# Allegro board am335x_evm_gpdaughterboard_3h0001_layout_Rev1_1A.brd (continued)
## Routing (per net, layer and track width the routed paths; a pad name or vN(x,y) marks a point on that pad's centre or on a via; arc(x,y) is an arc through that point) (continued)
NOR_A9: length 31.9
  TOP w0.121: v1(106.08,111.08) 119.41,111.08 120.55,109.93 U4.3 ; v2(105.15,96.97) U3.B6
  LY3 w0.102: v2(105.15,96.97) 105.57,97.4 105.57,98.59 106.8,99.82 106.8,102.53 106.32,103.01
  LY3 w0.121: v1(106.08,111.08) 106.08,103.25 106.32,103.01
NOR_A10: length 29.4
  TOP w0.121: v2(106.14,96.97) U3.A6 ; U4.5 119.75,109.94 119.05,110.63 106.95,110.63 v1(106.59,110.27)
  LY3 w0.102: v2(106.14,96.97) 106.72,97.54 106.72,98.72 107.23,99.22 107.23,102.65 106.87,103.01
  LY3 w0.121: 106.87,103.01 106.59,103.29 v1(106.59,110.27)
NOR_A11: length 27.6
  TOP w0.121: v1(104.05,105.83) 104.39,106.17 117.83,106.17 119.35,107.69 U4.6 ; v2(104.15,96.97) U3.C6
  LY3 w0.102: 104.2,103.01 104.69,102.53 104.69,99.07 103.75,98.13 103.75,97.36 v2(104.15,96.97)
  LY3 w0.121: 104.2,103.01 104.05,103.16 v1(104.05,105.83)
NOR_A12: length 16.2
  TOP w0.121: v2(103.15,96.97) U3.D6 ; v1(115.58,97.75) 115.68,97.65 115.91,97.65 116.36,97.2 116.37,97.2 116.55,97.02 U2.13
  LY6 w0.102: v2(103.15,96.97) 103.56,96.56 107.23,96.56 107.5,96.28
  LY6 w0.121: v1(115.58,97.75) 115.55,97.71 115.19,97.71 113.76,96.28 107.5,96.28
NOR_A13: length 14.4
  TOP w0.121: v2(105.15,95.97) U3.B7 ; U2.14 116.15,95.21 116.33,95.03 116.36,95.03 v1(116.55,94.83)
  LY6 w0.102: 107.7,95.54 105.61,95.54 105.53,95.62 105.5,95.62 v2(105.15,95.97)
  LY6 w0.121: v1(116.55,94.83) 115.46,95.92 108.08,95.92 107.7,95.54
NOR_A14: length 13.8
  TOP w0.102: v2(106.14,95.97) 106.19,95.92 107.5,95.92
  TOP w0.121: U2.16 115.35,97.3 115.01,97.64 115.01,98.81 114.75,99.07 111.01,99.07 107.86,95.92 107.5,95.92 ; v2(106.14,95.97) U3.A7
NOR_A15: length 14.1
  TOP w0.121: U2.17 v1(114.95,94.8) ; v2(104.15,95.97) U3.C7
  LY6 w0.102: 107.5,94.35 104.99,94.35 104.3,95.03 104.3,95.81 v2(104.15,95.97)
  LY6 w0.121: v1(114.95,94.8) 114.5,94.35 107.5,94.35
NOR_A16: length 17.7
  TOP w0.102: 107.5,94.29 107.48,94.27 102.78,94.27 102.24,94.81 102.24,96.06 U3.D7
  TOP w0.121: 107.5,94.29 111.6,98.4 113.77,98.4 114.11,98.06 114.11,97.52 114.15,97.48 U2.19
NOR_A17: length 19.5
  TOP w0.121: v1(100.82,92.98) 101.74,93.89 113.32,93.89 113.75,94.32 U2.20 ; v2(101.15,95.97) U3.E7
  LY3 w0.102: 100.34,94.21 100.34,94.88 101.15,95.68 v2(101.15,95.97)
  LY3 w0.121: 100.34,94.21 100.34,93.46 v1(100.82,92.98)
NOR_A18: length 12.6
  TOP w0.121: v1(113.58,97.7) 112.95,97.08 U2.22 ; v2(105.15,100.97) U3.B3
  LY6 w0.102: 107.5,98.86 107.26,98.86 v2(105.15,100.97)
  LY6 w0.121: 107.5,98.86 112.92,98.86 113.58,98.21 v1(113.58,97.7)
NOR_A19: length 12.2
  TOP w0.121: v2(104.15,99.97) U3.C4 ; U2.23 112.55,97.19 112.59,97.24 112.59,97.73 v1(112.81,97.95)
  LY6 w0.102: v2(104.15,99.97) 104.69,99.43 105.75,99.43 107.28,97.89 107.92,97.89
  LY6 w0.121: v1(112.81,97.95) 109.37,97.95 109.31,97.89 107.92,97.89
NOR_A20: length 26.3
  TOP w0.121: U4.8 118.55,107.31 117.85,106.61 v1(108.14,106.61) ; v2(103.15,97.97) U3.D5
  BOTTOM w0.102: 107.5,101.79 107.23,101.51 103.92,101.51 103.55,101.14 103.55,100.76 103.29,100.49 102.91,100.49 102.53,100.11 102.53,98.59 v2(103.15,97.97)
  BOTTOM w0.121: v1(108.14,106.61) 108.14,102.43 107.5,101.79
NOR_A21: length 23.6
  TOP w0.121: U4.9 118.15,107.73 118.19,107.69 118.19,107.31 117.94,107.05 112,107.05 111.98,107.04 111.61,107.04 111.6,107.05 109.17,107.05 v1(108.87,107.35) ; v2(103.15,99.97) U3.D4
  BOTTOM w0.102: v2(103.15,99.97) 103.67,100.49 107.23,100.49 107.5,100.77
  BOTTOM w0.121: v1(108.87,107.35) 108.87,104.68 108.59,104.39 108.59,101.85 107.5,100.77
NOR_A22: length 26.4
  TOP w0.102: 107.5,98.91 104.09,98.91 U3.C5 ; 109.95,99.48 109.39,98.91
  TOP w0.121: U4.11 v1(117.35,110.07) ; v1(115.51,98.64) 115.51,99.12 115.15,99.48 114.85,99.48 114.85,99.48 114.28,99.48 114.28,99.48 109.95,99.48 ; 109.39,98.91 107.5,98.91
  LY3 w0.121: v1(115.51,98.64) 116.19,99.33 116.19,104.63 117.13,105.57 117.13,109.85 v1(117.35,110.07)
NOR_A23: length 23.1
  TOP w0.102: v2(105.15,94.97) 107.5,94.97
  TOP w0.121: v1(116.34,107.5) 116.37,107.53 116.83,107.53 116.95,107.65 U4.12 ; v1(114.57,98.63) 113.94,98.63 113.93,98.64 111.25,98.64 107.58,94.97 107.5,94.97 ; v2(105.15,94.97) U3.B8
  BOTTOM w0.121: v1(116.34,107.5) 115.3,106.46 115.3,100.6 114.57,99.86 v1(114.57,98.63)
NOR_BYTEN: length 4.5
  TOP w0.121: v2(100.15,95.97) U3.F7
  BOTTOM w0.102: v2(100.15,95.97) 100.15,94.82 100.15,94.21
  BOTTOM w0.121: R259.2 100.11,92.37 R14.1 100.15,93.92 100.15,94.21
NOR_CEN: length 129.8
  TOP w0.121: U43.C8 v2(96.34,76.13) ; U2.48 121.9,90.4 v1(121.96,90.33) ; v1(120.43,100.01) 121.35,100.93 U4.48 ; v1(112.15,101.84) U4.25 ; U2.25 v1(111.54,90.4) 101.43,90.4 100.99,89.95 93.76,89.95 93.32,90.4 v1(92.87,90.4) U6.48 ; U6.25 v1(82.21,90.4) ; v2(100.15,101.97) U3.F2
  LY3 w0.121: v1(112.15,101.84) 111.1,100.79 111.1,90.84 v1(111.54,90.4)
  LY6 w0.102: v2(102.15,100.96) 102.15,102.15 ; 102.15,102.15 102.4,102.15 103.26,103.01 ; 102.15,102.15 101.89,102.4 100.75,102.4 100.32,101.97 v2(100.15,101.97)
  LY6 w0.121: v1(79.2,90.4) v1(82.21,90.4) 82.65,90.4 82.71,90.33 92.37,90.33 92.43,90.4 v1(92.87,90.4) ; v1(121.96,90.33) 118.63,90.33 118.57,90.4 v1(111.54,90.4) ; v1(89.11,84.68) 88.5,85.29 84.67,85.29 83.92,84.54 82.92,84.54 82.08,85.38 v1(79.2,85.38) ; 103.26,103.01 103.35,103.09 106.79,103.09 108.01,101.87 108.95,101.87 112.12,101.87 v1(112.15,101.84) 112.15,101.79 113.45,100.49 116.75,100.49 117.23,100.01 v1(120.43,100.01)
  BOTTOM w0.102: 89.74,78.65 89.74,71.13 90.14,70.73 95.53,70.73 95.73,70.93 95.73,75.52 v2(96.34,76.13)
  BOTTOM w0.121: v1(89.11,84.68) 88.8,84.37 88.8,79.53 89.44,78.9 89.49,78.9 89.74,78.65 ; v1(79.2,90.4) v1(79.2,85.38)
  BOTTOM w0.381: R15.1 v2(102.15,100.96)
NOR_D0: length 18.1
  TOP w0.121: U6.2 v1(91.74,97.51) ; v2(101.15,100.97) U3.E3
  LY3 w0.121: v1(91.74,100.77) v1(91.74,97.51)
  LY6 w0.102: 100.75,100.29 100.74,100.28 100.74,100.14 ; 100.75,100.29 100.75,100.57 v2(101.15,100.97) ; 100.75,100.29 100.75,100.15 100.74,100.14 ; 100.74,100.14 100.74,99.6 100.49,99.35 99.99,99.35 99.73,99.61 99.73,101.13 99.48,101.38 96.6,101.38
  LY6 w0.121: 96.6,101.38 95.8,101.38 95.18,100.77 v1(91.74,100.77)
NOR_D1: length 13.8
  TOP w0.102: v2(98.15,100.97) 96.6,100.97
  TOP w0.121: v2(98.15,100.97) U3.H3 ; 96.6,100.97 95.73,100.97 93.57,98.81 93.57,95.42 92.43,94.27 91.93,94.27 v1(91.34,94.86) U6.3
NOR_D2: length 18.7
  TOP w0.121: v2(101.15,99.97) U3.E4 ; U6.5 v1(90.54,94.72)
  LY6 w0.102: v2(101.15,99.97) 102.02,99.1 102.02,95.8 101.59,95.36 97.96,95.36 97.93,95.39 97.6,95.39 97.45,95.24 96.89,95.24 96.78,95.35 96.6,95.35
  LY6 w0.121: 96.6,95.35 91.18,95.35 v1(90.54,94.72)
NOR_D3: length 12.5
  TOP w0.121: U6.6 v1(90.14,97.51) ; v2(98.15,99.97) U3.H4
  LY6 w0.102: v2(98.15,99.97) 96.6,99.97
  LY6 w0.121: 96.6,99.97 90.91,99.97 89.64,98.7 89.64,98.02 v1(90.14,97.51)
NOR_D4: length 11.6
  TOP w0.121: v2(98.15,97.97) U3.H5 ; v1(90.08,98.46) 89.34,97.72 U6.8
  LY6 w0.102: v2(98.15,97.97) 96.6,97.97
  LY6 w0.121: v1(90.08,98.46) 90.57,97.97 96.6,97.97
NOR_D5: length 17.8
  TOP w0.121: U6.9 v1(88.94,94.72) ; v2(101.15,97.97) U3.E5
  LY6 w0.102: v2(101.15,97.97) 101.76,97.35 101.76,95.92 101.42,95.58 98.04,95.58 98.02,95.6 96.61,95.6 96.6,95.6
  LY6 w0.121: 96.6,95.6 89.83,95.6 v1(88.94,94.72)
NOR_D6: length 13.9
  TOP w0.102: v2(98.15,96.97) 96.77,95.6 96.6,95.6
  TOP w0.121: v2(98.15,96.97) U3.H6 ; 96.6,95.6 95.23,95.6 93.4,93.76 v1(88.94,93.76) 88.14,94.56 U6.11
NOR_D7: length 18.7
  TOP w0.121: v2(101.15,96.97) U3.E6 ; U6.12 87.74,97.77 v1(88.43,98.46)
  LY6 w0.102: v2(101.15,96.97) 100.75,97.36 100.75,97.79 100.74,97.8 100.74,98.22 100.74,98.22 100.74,98.85 100.49,99.1 99.86,99.1 99.48,99.48 97.32,99.48 96.74,98.9 96.6,98.9
  LY6 w0.121: v1(91.13,99.34) 91.57,98.9 96.6,98.9
  BOTTOM w0.121: v1(91.13,99.34) 89.31,99.34 v1(88.43,98.46)
NOR_D8: length 23.8
  TOP w0.121: v1(86.52,93.89) 87.34,94.71 U6.13 ; v2(100.15,100.97) U3.F3
  LY3 w0.102: v2(100.15,100.97) 100.62,100.49 100.62,95.54 99.74,94.66 v2(99.74,94.65)
  LY6 w0.102: v2(99.74,94.65) 99.29,94.21
  LY6 w0.121: 99.29,94.21 99.14,94.06 97.74,94.06 97.59,94.2 87.87,94.2 87.55,93.89 v1(86.52,93.89)
NOR_D9: length 15.8
  TOP w0.121: v2(99.15,100.97) U3.G3 ; U6.14 v1(86.94,97.51)
  LY6 w0.102: 96.6,100.56 98.74,100.56 v2(99.15,100.97)
  LY6 w0.121: v1(86.94,97.51) 87.88,98.45 87.88,98.57 89.53,100.22 95.54,100.22 95.89,100.56 96.6,100.56
NOR_D10: length 21.6
  TOP w0.121: U6.16 86.14,97.7 v1(86.91,98.46) ; v2(100.15,99.97) U3.F4
  LY6 w0.102: v2(100.15,99.97) 100.54,100.37 100.54,100.66 100.62,100.73 100.62,101.26 100.31,101.56 99.98,101.56 99.74,101.8 99.74,101.91 99.55,102.09 99.55,102.14 99.31,102.38 97.96,102.38 97.96,102.37 97.7,102.37 97.15,101.83 96.6,101.83
  LY6 w0.121: 96.6,101.83 95.48,101.83 94.91,101.26 88.2,101.26 87.57,100.62 87.57,99.12 v1(86.91,98.46)
NOR_D11: length 26.6
  TOP w0.121: v1(85,93.89) 85.74,94.63 U6.17 ; v2(99.15,99.97) U3.G4
  LY6 w0.121: v1(100.79,93.77) 89.75,93.77 89.17,93.19 85.7,93.19 v1(85,93.89)
  BOTTOM w0.102: 100.79,94.21 100.74,94.25 100.74,98.73 99.49,99.97 v2(99.15,99.97)
  BOTTOM w0.121: 100.79,94.21 v1(100.79,93.77)
NOR_D12: length 18.9
  TOP w0.121: v2(100.15,97.97) U3.F5 ; U6.19 v1(84.94,94.86)
  LY6 w0.102: 96.6,96.34 96.63,96.36 99.28,96.36 99.73,96.81 99.73,97.56 v2(100.15,97.97)
  LY6 w0.121: v1(84.94,94.86) 86.42,96.34 96.6,96.34
NOR_D13: length 18.4
  TOP w0.121: U6.20 84.54,97.75 v1(85.25,98.46) ; v2(99.15,96.97) U3.G6
  LY6 w0.102: 96.6,96.6 96.63,96.58 98.75,96.58 v2(99.15,96.97)
  LY6 w0.121: 96.6,96.6 86.79,96.6 86.03,97.36 86.03,97.69 v1(85.25,98.46)
NOR_D14: length 23.4
  TOP w0.121: v2(100.15,96.97) U3.F6 ; U6.22 v1(83.74,97.51)
  LY6 w0.102: 96.6,96.93 97.18,96.93 97.63,97.38 98.52,97.38 98.72,97.57 98.72,98.34 98.84,98.46 100.23,98.46 100.54,98.15 100.54,98.14 100.54,98.13 100.54,97.81 100.54,97.8 100.54,97.36 v2(100.15,96.97)
  LY6 w0.121: v1(83.74,97.51) 83.74,97.95 84.69,98.9 85.45,98.9 86.34,98.01 86.34,97.44 86.85,96.93 96.6,96.93
NOR_D15: length 16.3
  TOP w0.121: R249.1 95.6,93.32 84.3,93.32 v1(82.97,94.65) 83.34,95.02 U6.23
NOR_D15A0: length 5.9
  TOP w0.102: v2(99.15,95.97) 99.15,94.65 98.7,94.21
  TOP w0.121: v2(99.15,95.97) U3.G7 ; 98.7,94.21 98.59,94.1 98.59,92.49 R250.2 R249.2
NOR_OEN: length 50.8
  TOP w0.102: 96.6,102.41 96.64,102.37 97.97,102.37 98.46,102.86 98.84,102.86 99,102.71 99,102.11 v2(99.15,101.97)
  TOP w0.121: 92.58,98.9 84.17,98.9 v1(82.71,97.45) 82.94,97.22 U6.24 ; 92.58,98.9 92.58,95.16 v1(92.14,94.72) U6.1 ; 92.58,98.9 96.09,102.41 96.6,102.41 ; v2(99.15,101.97) U3.G2 ; U43.C9 v2(97.34,76.13)
  LY6 w0.102: v2(97.34,76.13) 97.34,76.35 96.94,76.75 96.94,78.37 97.04,78.47 97.04,78.65
  LY6 w0.121: v1(96.32,84.61) 97.04,83.9 97.04,78.65 ; v1(95.44,94.72) v1(92.14,94.72)
  BOTTOM w0.121: v1(95.44,94.72) 95.94,94.21 95.94,88.73 96.09,88.58 96.09,84.84 v1(96.32,84.61)
NOR_READY: length 38.6
  TOP w0.102: U3.A4 105.29,99.11 103.39,99.11 v2(103.15,98.87)
  TOP w0.121: U43.C14 v2(103.33,76.13)
  BOTTOM w0.102: v2(103.33,76.13) 103.75,76.13 104.15,75.73 106.54,75.73 106.74,75.93 106.74,76.12 107.19,76.57 107.86,76.57 ; v2(103.15,98.87) 103.55,98.46 103.55,97.57 103.68,97.45 104.56,97.45 104.69,97.57 104.69,98.34 104.94,98.59 106.1,98.59 106.55,98.14 106.55,98.11 107.1,97.56 107.5,97.56 107.5,97.57
  BOTTOM w0.121: 107.86,76.57 108.16,76.57 109.04,77.46 109.04,78.2 108.69,78.56 108.69,88.49 108.99,88.79 108.99,90.07 109.26,90.33 109.26,96.42 108.11,97.57 107.5,97.57
NOR_RESETN: length 31.5
  TOP w0.121: U43.C13 v2(102.33,76.13) ; v2(105.15,97.97) U3.B5
  LY6 w0.102: v2(102.33,76.13) 101.94,75.73 101.94,74.93 102.14,74.73 102.54,74.73 102.93,75.13 102.93,76.32 103.13,76.52 104.29,76.52 104.73,76.96 104.73,78.65
  LY6 w0.121: 104.73,78.65 104.73,79.22 106.09,80.58 v1(107.23,80.58)
  BOTTOM w0.102: v2(105.15,97.97) 105.57,97.54 105.57,96.94 105.96,96.56 106.46,96.56 107.4,95.62 107.4,94.21
  BOTTOM w0.121: 107.4,94.21 107.4,90.42 107.67,90.15 107.67,81.02 v1(107.23,80.58)
NOR_WEN: length 33.8
  TOP w0.121: U43.C7 v2(95.34,76.13) ; v2(106.14,97.97) U3.A5
  LY3 w0.102: 105.7,94.21 105.7,97.07 105.75,97.12 105.75,97.13 106.14,97.53 v2(106.14,97.97)
  LY3 w0.121: 105.7,94.21 105.7,92.91 105.03,92.24 v1(105.03,88.39)
  LY6 w0.102: v2(95.34,76.13) 95.34,76.57 94.94,76.96 94.94,77.85 94.73,78.07 94.73,78.65
  LY6 w0.121: v1(93.38,80.56) 94.73,79.21 94.73,78.65
  BOTTOM w0.121: v1(105.03,88.39) 105.03,86.91 102.44,84.32 102.44,82.48 100.2,80.24 99.03,80.24 98.75,80.52 93.42,80.52 v1(93.38,80.56)
PMIC_PWR_EN: length 148.1
  TOP w0.121: R11.2 34.07,94.02 J1.25 ; v1(40.74,140.56) 94.28,140.56 95.13,141.42 97.7,141.42 104.05,147.77 v1(104.05,151.04) R242.2 ; v1(121.83,150.91) R238.2
  LY3 w0.121: v1(40.74,140.56) 40.74,123.96 40.16,123.38 40.16,91.95 39.6,91.39 38.52,91.39 37.36,92.55 35.54,92.55 J1.25
  LY6 w0.121: v1(104.05,151.04) 104.62,150.47 121.39,150.47 v1(121.83,150.91)
RS232_1_CTS: length 25.7
  TOP w0.121: U15.8 v1(16.17,130.47)
  LY3 w0.121: v1(16.17,130.47) 16.17,117.26 10.69,111.78 J10.8
RS232_1_RTS: length 24.3
  TOP w0.121: U15.7 v1(16.04,131.74)
  LY3 w0.121: J10.7 11.17,114.55 15.02,118.4 15.02,130.72 v1(16.04,131.74)
RS232_1_RXD: length 24.3
  TOP w0.121: U15.13 v1(17.56,135.55)
  LY3 w0.121: J10.2 10.41,115.95 14.64,120.18 14.64,132.63 v1(17.56,135.55)
RS232_1_TXD: length 28.7
  TOP w0.121: U15.14 v1(17.69,136.82)
  LY3 w0.121: v1(17.69,136.82) 18.2,136.31 18.2,133.26 15.4,130.47 15.4,118.15 10.43,113.17 J10.3
RS232_2_CTS: length 20.9
  TOP w0.121: v1(153.96,46.9) U19.8 ; J12.8 v1(165.53,56.39)
  BOTTOM w0.121: v1(165.53,56.39) 158.03,48.88 153.99,48.88 153.43,48.32 153.43,47.61 153.96,47.08 v1(153.96,46.9)
RS232_2_RTS: length 18.1
  TOP w0.121: v1(153.96,48.17) U19.7 ; J12.7 v1(165.66,53.59)
  BOTTOM w0.121: v1(165.66,53.59) 159.68,47.61 154.52,47.61 v1(153.96,48.17)
RS232_2_RXD: length 10.7
  TOP w0.121: U19.13 160.41,51.98 160.64,52.21 J12.2
RS232_2_TXD: length 11.3
  TOP w0.121: U19.14 161.12,53.25 162.85,54.98 J12.3
RS232_3_CTS: length 21.9
  TOP w0.121: v1(153.96,78.02) U22.8 ; J14.8 v1(165.43,87.48)
  BOTTOM w0.121: v1(165.43,87.48) 159.14,81.19 154.09,81.19 152.97,80.07 152.97,79.01 v1(153.96,78.02)
RS232_3_RTS: length 17.6
  TOP w0.121: v1(153.96,79.29) U22.7 ; J14.7 v1(165.25,84.71)
  BOTTOM w0.121: v1(165.25,84.71) 160.51,79.97 154.65,79.97 v1(153.96,79.29)
RS232_3_RXD: length 10.7
  TOP w0.121: J14.2 159.27,83.32 159.04,83.1 U22.13
RS232_3_TXD: length 11.3
  TOP w0.121: 157.25,84.37 161,84.37 162.72,86.09 J14.3
SDMMC1_CD: length 138.4
  TOP w0.102: U43.V9 97.84,59.6
  TOP w0.121: U27.3 82.96,152.94 82.71,152.69 80.3,152.69 79.42,151.81 79.42,148.63 79.03,148.25 v1(78.65,148.25) R57.1 ; v1(98.46,55.03) 97.84,55.66 97.84,59.6
  LY3 w0.121: v1(74.21,54.9) 74.21,67.6 74.53,67.92 74.53,71.34 74.26,71.61 74.26,81.38 74.27,81.38 74.27,106.77 73.82,107.21 73.82,133.39 77.12,136.69 77.12,146.72 v1(78.65,148.25)
  LY6 w0.121: v1(98.46,55.03) 98.34,55.03 97.83,54.52 74.59,54.52 v1(74.21,54.9)
  BOTTOM w0.121: J15.15 79.03,149.77 79.03,148.45 78.82,148.25 v1(78.65,148.25)
SDMMC1_CLK: length 43.9
  TOP w0.121: 93.77,154.22 93.77,150.91 91.23,148.37 v1(90.31,148.37) ; U23.19 90.61,145.94 89.95,146.6 89.7,146.6 89.57,146.72 89.57,148.63 89.45,148.75 89.06,148.75 88.94,148.63 88.94,146.72 88.81,146.6 88.3,146.6 88.18,146.72 88.18,148.37 88.05,148.5 87.67,148.5 87.54,148.37 87.54,146.72 87.41,146.6 87.08,146.6 86.96,146.72 v1(86.96,148.37)
  LY6 w0.121: v1(86.96,148.37) 86.4,148.37 86.27,148.25 86.27,146.95 86.4,146.82 87.41,146.82 87.54,146.95 87.54,148.37 87.67,148.5 88.05,148.5 88.18,148.37 88.18,146.85 88.3,146.72 88.81,146.72 88.94,146.85 88.94,148.25 89.06,148.37 89.57,148.37 89.7,148.25 89.7,146.72 89.83,146.6 89.95,146.6 90.08,146.47 90.08,145.58 90.21,145.45 91.94,145.45 92.07,145.58 92.07,146.03 91.94,146.15 90.84,146.15 90.72,146.28 90.72,146.95 90.59,147.07 90.43,147.07 90.31,147.2 v1(90.31,148.37)
  BOTTOM w0.121: J15.5 v1(86.96,148.37) ; v1(90.31,148.37) J15.20
SDMMC1_CMD: length 43.2
  TOP w0.121: U23.20 90.09,145.44 v1(89.57,145.96) ; R49.1 83.73,148.37 v1(83.61,148.25) ; U25.7 94.78,155.99 v1(95.03,156.25)
  LY3 w0.121: v1(95.29,149.77) 95.29,154.7 95.31,154.72 95.31,155.03 95.29,155.05 95.29,155.99 v1(95.03,156.25)
  LY6 w0.121: v1(95.29,149.77) 96.3,149.77 96.43,149.9 96.43,150.53 96.3,150.66 95.92,150.66 95.8,150.79 95.8,151.04 95.67,151.17 95.29,151.17 95.16,151.04 95.16,150.53 95.03,150.41 94.78,150.41 94.65,150.53 94.65,151.42 94.53,151.55 94.14,151.55 94.02,151.42 94.02,150.41 93.89,150.28 93.51,150.28 93.38,150.41 93.38,151.42 93.26,151.55 92.87,151.55 92.75,151.42 92.75,150.79 92.62,150.66 84.24,150.66 v1(83.61,151.29) ; v1(83.61,148.25) 83.61,146.54 84.52,145.63 86.22,145.63 86.35,145.76 86.35,146.34 86.47,146.47 89.06,146.47 v1(89.57,145.96)
  BOTTOM w0.121: v1(83.61,148.25) J15.17 v1(83.61,151.29) ; J15.2 v1(95.29,149.77)
SDMMC1_DAT0: length 44.1
  TOP w0.121: v1(91.1,147.36) 91.86,147.36 91.99,147.23 91.99,146.69 U23.18 ; v1(92.59,148.37) 92.59,148.75 94.27,150.43 94.27,154.22 ; R50.1 82.03,148.83 v1(82.03,148.2)
  LY6 w0.121: v1(92.59,148.37) 92.59,149.77 92.47,149.9 92.11,149.9 91.99,149.77 91.99,147.93 91.92,147.87 90.97,147.87 90.84,147.99 90.84,148.75 90.72,148.88 79.67,148.88 79.54,148.75 79.54,148.32 79.67,148.2 v1(82.03,148.2)
  BOTTOM w0.121: J15.22 92.8,148.5 92.68,148.37 v1(92.59,148.37) ; v1(91.1,147.36) 88.56,147.36 87.16,145.96 83.73,145.96 83.35,146.34 82.46,146.34 82.33,146.47 82.33,147.89 v1(82.03,148.2) J15.7
SDMMC1_DAT1: length 59.3
  TOP w0.121: U23.16 93,147.36 93.38,147.74 93.67,147.74 93.91,147.99 95.03,147.99 v1(95.29,148.25) ; R51.1 79.92,150.48 79.98,150.54 79.98,151.1 v1(80.3,151.42) ; v1(93.51,148.37) 94.78,149.64 94.78,154.22
  LY3 w0.121: v1(93.51,148.37) 93.51,148.69 93.38,148.81 88.43,148.81 88.3,148.94 88.3,149.39 88.43,149.52 93.64,149.52 93.76,149.64 93.76,150.02 93.64,150.15 88.43,150.15 88.3,150.28 88.3,150.72 88.43,150.84 93.13,150.84 93.26,150.97 93.26,152.06 93.38,152.18 94.4,152.18 94.53,152.06 94.53,148.5 94.78,148.25 v1(95.29,148.25)
  LY6 w0.121: v1(80.3,151.42) 81.06,150.66 83.48,150.66 83.86,150.28 92.87,150.28 93.51,149.64 v1(93.51,148.37)
  BOTTOM w0.121: v1(80.3,151.42) 80.33,151.39 J15.8 ; J15.23 93.51,149.67 v1(93.51,148.37)
SDMMC1_DAT2: length 43.7
  TOP w0.121: R52.1 81.18,150.29 v1(81.18,151.41) ; U25.6 96.81,155.49 97.57,154.72 97.57,153.07 99.07,151.58 v1(99.48,151.17) ; v1(90.47,143.94) U23.23
  LY6 w0.121: v1(90.47,143.94) 89.95,143.94 88.81,145.08 84.01,145.08 81.86,147.23 v1(81.83,147.23) ; v1(81.18,151.41) 81.87,152.1 98.04,152.1 98.97,151.17 v1(99.48,151.17)
  BOTTOM w0.121: J15.9 99.48,149.79 v1(99.48,151.17) ; v1(81.18,151.41) J15.24 81.18,147.88 v1(81.83,147.23)
SDMMC1_DAT3: length 44.5
  TOP w0.121: U23.22 90.08,144.44 v1(89.57,144.94) ; U25.8 94.27,155.99 v1(94.02,156.25) ; v1(96.96,151.28) 96.96,150.39 R48.1
  LY3 w0.121: v1(96.96,151.28) 96.96,155.34 95.61,156.69 94.46,156.69 v1(94.02,156.25)
  LY6 w0.121: v1(96.96,151.28) 96.97,151.29 98.34,151.29 98.46,151.17 98.46,150.79 98.34,150.66 96.68,150.66 95.49,151.85 88.35,151.85 88.18,151.68 87.46,151.68 87.29,151.85 83.4,151.85 v1(82.84,151.29) ; v1(82.81,147.13) 82.81,146.63 84.11,145.33 87.08,145.33 87.72,145.96 88.93,145.96 89.57,145.31 v1(89.57,144.94)
  BOTTOM w0.121: v1(82.84,151.29) 82.84,149.8 J15.16 v1(82.81,147.13) ; v1(96.96,151.28) J15.1
SDMMC1_DAT4: length 36.3
  TOP w0.121: v1(88.68,154.22) 89.33,154.22 89.33,153.31 89.63,153.01 91.54,153.01 92.42,153.89 92.42,156.19 90.84,157.77 90.84,163.11 R53.1 91.35,164.5 92.05,165.2 95.35,165.2 v1(95.8,165.65) ; 84.62,145.58 v1(84.62,147.99)
  LY3 w0.121: v1(84.62,147.99) 84.62,149.77 85.49,150.64 85.49,150.65 85.75,150.91 85.75,151.56 85.62,151.68 84.87,151.68 84.75,151.81 84.75,153.33 84.87,153.45 85.64,153.45 85.76,153.58 85.76,154.09 85.89,154.22 v1(88.68,154.22)
  BOTTOM w0.121: v1(95.8,165.65) 95.8,166.71 J15.10
SDMMC1_DAT5: length 35.6
  TOP w0.121: v1(93.23,165.65) 90.97,165.65 90.08,164.76 R54.1 90.59,163.11 90.59,157.64 92.17,156.06 92.17,154.15 91.48,153.45 v1(90.08,153.45) 89.83,153.71 89.83,154.21 89.83,154.22 ; v1(85.76,147.99) R252.1
  LY3 w0.121: v1(85.76,147.99) 85.76,148.88 86.14,149.26 87.29,149.26 87.41,149.39 87.41,149.77 87.29,149.9 86.14,149.9 86.02,150.02 86.02,152.06 85.89,152.18 85.13,152.18 85,152.31 85,152.69 85.13,152.82 86.27,152.82 86.4,152.95 86.4,153.33 86.52,153.45 v1(90.08,153.45)
  BOTTOM w0.121: v1(93.23,165.65) J15.11
SDMMC1_DAT6: length 33.4
  TOP w0.121: R253.1 79.41,146.47 v1(78.65,147.23) ; U26.7 90.33,156.24 v1(90.46,156.37) 90.33,156.5 90.33,157.65 88.3,159.68 88.3,163.11 R55.1 88.81,164.76 87.92,165.65 v1(85.73,165.65)
  LY3 w0.121: v1(90.46,156.37) 90.02,156.82 88.24,156.82 88.04,156.62 87.18,156.62 80.94,150.38 80.94,149.52 v1(78.65,147.23)
  BOTTOM w0.121: J15.12 v1(85.73,165.65)
SDMMC1_DAT7: length 33.9
  TOP w0.121: R254.1 80.68,147.23 v1(80.17,147.74) ; v1(83.22,165.65) 83.66,165.2 87.09,165.2 87.54,164.76 R56.1 88.05,163.11 88.05,159.55 89.83,157.77 89.83,156.5 v1(89.7,156.37) 89.83,156.24 U26.8
  LY3 w0.121: v1(89.7,156.37) 87.29,156.37 83.73,152.82 83.73,152.44 83.86,152.31 84.11,152.31 84.24,152.18 84.24,151.93 84.11,151.8 82.71,151.8 81.19,150.28 81.19,148.75 v1(80.17,147.74)
  BOTTOM w0.121: J15.13 83.22,166.76 v1(83.22,165.65)
SDMMC1_WP: length 126.4
  TOP w0.121: U27.5 77.67,155.53 77,154.85 v1(77,149.77) ; v2(92.34,62.12) U43.T4
  LY3 w0.121: v1(77,149.77) 75.09,147.87 75.09,144.31 70.38,139.6 70.38,108.56 70.77,108.17 70.77,88.76 70.12,88.11 70.12,63.03 v1(69.61,62.52)
  LY6 w0.102: 88.81,61.53 91.74,61.53 v2(92.34,62.12)
  LY6 w0.121: v1(69.61,62.52) 70.24,63.16 79.67,63.16 80.56,62.27 81.57,62.27 81.83,62.01 88.05,62.01 88.53,61.53 88.81,61.53
  BOTTOM w0.121: v1(77,149.77) J15.14
SMA_AIN1: length 38.2
  TOP w0.121: R42.1 32.8,134.28 32.42,134.66 32.42,136.69 22.9,146.21 6.9,146.21 5.81,145.13 J9.1
SPIMEM_CLK: length 18.8
  TOP w0.102: 88.81,69 89.18,68.63 U43.K1
  TOP w0.121: U8.6 v1(74.97,70.4) ; 88.81,69 88.3,69.51 88.3,70.14 87.85,70.6 85.47,70.6 84.4,71.67 v1(83.22,71.67)
  LY6 w0.121: v1(74.97,70.4) 76.87,70.4 77.51,71.03 79.03,71.03 79.29,70.78 82.33,70.78 v1(83.22,71.67)
SPIMEM_CS: length 26.3
  TOP w0.102: 88.81,68.02 90.99,68.02 91,68.03 92.24,68.03 U43.K4
  TOP w0.121: 88.81,68.02 88.77,68.02 87.79,69 87.29,69 87.04,69.24 83.88,69.24 81.45,71.67 v1(81.44,71.67) ; 69.32,72.94 v1(70.9,72.94)
  LY6 w0.121: v1(81.44,71.67) 81.32,71.67 80.3,72.68 76.75,72.68 75.86,73.57 71.54,73.57 v1(70.9,72.94)
SPIMEM_DI: length 20.2
  TOP w0.102: U43.K2 90.44,69.02 89.3,69.02 88.81,69.51
  TOP w0.121: U8.5 v1(75.09,69.13) ; 88.81,69.51 88.56,69.76 88.56,70.27 87.98,70.84 85.57,70.84 84.31,72.11 80.74,72.11 v1(80.3,71.67)
  BOTTOM w0.121: v1(80.3,71.67) 79.12,71.67 76.58,69.13 v1(75.09,69.13)
SPIMEM_DO: length 25.3
  TOP w0.102: U43.K3 91.65,68.63 91.26,68.23 89.2,68.23
  TOP w0.121: 89.2,68.23 87.98,69.45 87.48,69.45 87.23,69.7 87.23,70.07 86.97,70.33 85.39,70.33 85.14,70.58 83.42,70.58 v1(82.33,71.67) ; U8.2 v1(70.9,71.67)
  LY6 w0.121: v1(70.9,71.67) 71.54,72.3 78.52,72.3 79.67,71.16 81.83,71.16 v1(82.33,71.67)
SPIMEM_HOLDN: length 17.4
  TOP w0.102: 88.81,67.63 U43.L1
  TOP w0.121: 88.81,67.63 88.28,67.63 86.91,68.99 83.49,68.99 81.78,70.71 79.35,70.71 78.4,71.67 U8.7 v1(74.97,71.67)
  BOTTOM w0.121: v1(74.97,71.67) R22.1
SPIMEM_WPN: length 25.9
  TOP w0.121: R21.1 U8.3 v1(70.9,70.4) ; v1(81.44,70.27) 82.97,68.74 86.78,68.74 88.18,67.35 89.45,67.35 89.67,67.13 90.33,67.13 U43.L2
  LY6 w0.121: v1(70.9,70.4) 71.41,69.89 77.13,69.89 77.87,70.63 78.88,70.63 79.24,70.27 v1(81.44,70.27)
SYS_RESETN: length 244.8
  TOP w0.121: v1(47.22,90.14) 41.25,90.14 39.28,92.11 R10.2 37.25,93.38 J1.26 ; v1(30.92,140.91) 30.92,141.4 33.65,144.13 50.24,144.13 v1(55.24,149.14) R232.2 ; R156.2 v1(99.61,53.25) ; U39.3 v1(54.82,37.23) ; U40.3 v1(54.82,27.07)
  LY3 w0.121: J1.26 35.21,95.42 35.21,96.81 34.58,97.44 33.81,97.44 29.62,101.63 29.62,130.62 30.92,131.92 v1(30.92,140.91) ; v1(54.82,27.07) 54.82,34.36 55.26,34.8 55.26,35.16 54.82,35.6 v1(54.82,37.23) ; v1(99.73,45.63) 99.73,49.19 98.53,50.39 98.53,52.17 v1(99.61,53.25)
  LY6 w0.121: v1(47.22,90.14) 47.22,89.46 47.79,88.89 58.5,88.89 62.12,85.27 62.12,82.33 65.55,78.9 67.35,78.9 68.54,77.71 80.86,77.71 v1(81.57,77) ; v1(54.82,37.23) 56.16,38.57 70.77,38.57 74.33,42.13 74.33,43.31 75.5,44.49 98.34,44.49 98.46,44.61 98.72,44.61 v1(99.73,45.63)
  BOTTOM w0.121: v1(99.61,53.25) 86.46,53.25 83.73,55.98 83.73,72.3 83.53,72.5 83.53,75.04 v1(81.57,77)
SYS_WARMRESETN: length 13.8
  BOTTOM w0.121: TP2.1 47.81,107.86 43.85,107.86 43.2,108.51 43.2,110.29 J2.11
TEMP_ALERT: length 106.2
  TOP w0.121: U13.3 v1(63.74,97.32) 63.74,96.87 R31.1 ; v1(92.82,45.16) 92.15,44.49 64.74,44.49 v1(63.47,43.22) ; v2(93.34,61.12) U43.U5
  LY3 w0.102: v2(93.34,61.12) 93.93,60.53 93.93,59.89
  LY3 w0.121: v1(63.47,43.22) 63.47,70.2 66.06,72.8 66.06,77.61 65.04,78.63 65.04,88.05 64.23,88.86 64.23,96.82 v1(63.74,97.32) ; 93.93,59.89 93.64,59.6 93.64,45.97 v1(92.82,45.16)
TSC_AIN0: length 161.5
  TOP w0.121: v1(38.65,135.8) R34.2
  LY3 w0.095: 106.34,120.81 106.34,122.21 ; 120.81,56.68 122.21,56.68
  LY3 w0.121: 106.34,120.81 J21.14 107.35,119.8 107.35,118.66 108.76,117.25 114.94,117.25 123.23,108.96 123.23,57.13 122.78,56.68 122.21,56.68 ; v1(106.08,133.64) 106.34,133.39 106.34,132.98 106.58,132.73 106.58,124.14 106.02,123.58 106.02,122.65 106.34,122.34 106.34,122.21 ; 120.18,56.04 120.81,56.68
  BOTTOM w0.121: v1(38.65,135.8) 39.15,135.29 47.57,135.29 48.96,133.9 56.29,133.9 57.06,133.13 59.84,133.13 60.73,134.02 71.7,134.02 72.71,133.01 105.45,133.01 v1(106.08,133.64)
TSC_AIN1: length 183.2
  TOP w0.121: R42.2 R35.2 30.91,132.63 29.64,131.36 29.64,123.98 33.06,120.56 45,120.56 45.9,119.66 45.9,119.43 55.75,109.58 63.82,109.58 67.49,113.25 103.45,113.25 107.29,117.09 107.29,118.74 107.73,119.18 108.24,119.18 ; 108.24,119.18 J21.16 ; 108.24,119.18 108.86,119.18 109.56,118.48 109.56,117.18 111.5,115.24 121.86,115.24 124.63,112.47 124.63,70.66 118.78,64.81 118.78,55.04 119.05,54.77 120.18,54.77
TSC_AIN2: length 171.3
  TOP w0.121: R38.2 v1(31.03,130.09)
  LY3 w0.095: 120.81,54.14 122.21,54.14 ; 108.88,121.07 108.88,122.21
  LY3 w0.121: 108.88,121.07 109.51,120.43 J21.18 109.51,118.66 110.17,117.99 115.25,117.99 115.76,117.49 124.01,109.23 124.01,55.94 122.21,54.14 ; 108.88,122.21 108.88,122.34 109.26,122.72 109.26,124.74 109.13,124.87 109.13,128.69 108.37,129.45 v1(108.37,132.18) ; 120.18,53.5 120.81,54.14
  BOTTOM w0.121: v1(108.37,132.18) 105.77,132.18 105.73,132.22 72.46,132.22 72.41,132.27 71.44,133.23 70.82,133.23 70.55,133.23 70.14,133.23 61,133.23 60.15,132.39 57.37,132.39 56.75,132.39 55.98,133.16 51.49,133.16 50.52,132.18 39.97,132.18 38.7,130.91 38.69,130.91 37.86,130.09 v1(31.03,130.09)
TSC_AIN3: length 173
  TOP w0.121: R40.2 v1(31.03,128.82)
  LY3 w0.095: 120.81,52.87 122.08,52.87 ; 110.15,122.21 110.15,121.07
  LY3 w0.121: v1(109.64,130.85) 111.35,129.14 111.35,124.68 110.15,123.48 110.15,122.21 ; 122.08,52.87 124.5,55.29 124.5,108.82 124.5,109.44 116.54,117.4 115.45,118.49 111.58,118.49 110.78,119.29 J21.20 110.78,120.43 110.15,121.07 ; 120.18,52.23 120.81,52.87
  BOTTOM w0.121: v1(109.64,130.85) 109.63,130.85 109.62,130.85 109.18,131.29 108.82,131.29 108.62,131.49 108.08,131.49 107.97,131.61 105.64,131.61 105.53,131.72 72.25,131.72 72.2,131.77 71.24,132.74 70.35,132.74 61.61,132.74 61.2,132.74 60.61,132.15 60.36,131.89 57.57,131.89 56.55,131.89 56.29,132.15 55.78,132.66 51.7,132.66 48.29,129.26 31.47,129.26 v1(31.03,128.82)
TSC_AIN4: length 150.8
  TOP w0.121: v1(47.54,133.9) R36.1
  LY3 w0.095: 106.97,121.45 107.37,121.05 107.37,120.84 107.61,120.61 107.61,119.54
  LY3 w0.121: J7.13 123.04,56.04 123.48,56.49 123.48,109.06 115.04,117.5 108.89,117.5 107.73,118.66 107.73,119.42 107.61,119.54 ; 106.97,121.45 106.97,124.37 106.84,124.5 v1(106.84,133.13)
  BOTTOM w0.121: v1(47.54,133.9) 48.61,133.9 48.85,133.65 56.19,133.65 56.96,132.89 59.95,132.89 60.83,133.77 71.6,133.77 72.61,132.76 105.56,132.76 105.92,133.13 v1(106.84,133.13)
TSC_AIN5: length 151.8
  TOP w0.121: v1(47.54,132.63) R37.1
  LY3 w0.095: 108.88,119.54 108.88,120.74 108.64,120.97 108.64,121.05 108.24,121.45
  LY3 w0.121: 108.24,121.45 108.24,122.21 109,122.97 109,124.62 108.82,124.8 108.82,128.56 107.61,129.78 v1(107.61,132.63) ; J7.15 122.21,54.77 123.76,56.32 123.76,109.13 115.14,117.75 110.04,117.75 109.19,118.59 109.19,119.23 108.88,119.54
  BOTTOM w0.121: v1(107.61,132.63) 105.77,132.63 105.66,132.52 72.51,132.52 71.54,133.48 70.65,133.48 60.89,133.48 60.59,133.18 60.05,132.64 57.27,132.64 56.85,132.64 56.09,133.41 51.39,133.41 50.61,132.63 v1(47.54,132.63)
TSC_AIN6: length 153.1
  TOP w0.121: R39.1 v1(47.54,130.09)
  LY3 w0.095: 109.51,121.45 109.91,121.05 109.91,120.97 110.15,120.74 110.15,119.42
  LY3 w0.121: 109.51,121.45 109.51,124.84 109.43,124.92 109.43,128.9 109,129.32 v1(109,131.74) ; 110.15,119.42 111.32,118.24 115.35,118.24 115.86,117.73 124.26,109.34 124.26,108.93 124.26,55.55 122.21,53.5 J7.17
  BOTTOM w0.121: v1(47.54,130.09) 48.77,130.09 51.6,132.91 55.88,132.91 56.65,132.14 57.47,132.14 60.25,132.14 61.1,132.99 61.71,132.99 61.71,132.99 69.83,132.99 69.83,132.99 70.45,132.99 70.45,132.99 70.93,132.99 70.93,132.99 71.34,132.99 71.34,132.99 72.35,131.97 105.63,131.97 105.74,131.86 108.06,131.86 108.19,131.74 109,131.74 v1(109,131.74)
TSC_AIN7: length 156.1
  TOP w0.121: R41.1 v1(47.54,128.82)
  LY3 w0.121: v1(110.4,130.85) 110.4,130.5 111.6,129.3 111.6,124.55 110.78,123.74 110.78,121.45 111.43,120.8 111.43,119.71 111.42,119.7 111.42,119.29 111.97,118.74 115.56,118.74 116.06,118.23 124.75,109.54 124.75,109.13 124.75,108.72 124.75,108.72 124.75,54.62 122.37,52.23 J7.19
  BOTTOM w0.121: v1(47.54,128.82) 48.2,128.82 51.8,132.42 55.68,132.42 56.05,132.05 56.19,131.9 56.44,131.65 57.68,131.65 60.46,131.65 60.71,131.9 61.3,132.49 71.13,132.49 72.15,131.48 105.42,131.48 105.54,131.36 107.87,131.36 107.98,131.25 108.47,131.25 109.38,130.34 109.89,130.34 v1(110.4,130.85)
TSC_I2CSCL: length 74.4
  LY3 w0.121: 120.18,62.39 119.49,62.39 119.33,62.56 119.33,65.08 120.93,66.68 120.93,72.75 121.52,73.33 121.52,92.96 121.7,93.15 121.7,93.33 122.16,93.79 122.16,100.69 121.4,101.46 121.4,108.28 113.13,116.55 v1(112.61,116.55)
  LY6 w0.121: v1(112.61,116.55) 103.35,116.55 100.62,119.28 J21.4
TSC_I2CSDA: length 76.5
  LY3 w0.121: 120.18,61.12 119.3,61.12 118.79,61.63 118.79,84.5 119.04,84.75 v1(119.04,87.79)
  LY6 w0.121: J21.6 101.89,119.33 103.73,117.49 113.22,117.49 117.97,112.74 117.97,108.19 118.2,107.96 118.2,107.1 118.06,106.96 118.06,104.9 122.54,100.42 122.54,90.29 120.62,88.37 119.61,88.37 v1(119.04,87.79)
TSC_RSV1_VREF: length 2.4
  TOP w0.381: TP13.1 104.43,123.1 104.43,121.45
UART1_CTS: length 147.4
  TOP w0.121: v1(20.87,130.47) U15.9 ; v2(106.34,72.13) U43.G17
  LY3 w0.102: v2(106.34,72.13) 105.92,72.13 105.52,72.52 105.34,72.52 104.94,72.92 104.94,74.33 105.34,74.73 106.99,74.73 107.86,75.6
  LY3 w0.121: 107.86,75.6 108.14,75.88 108.14,78.19 108.69,78.74 108.69,87.68 109.27,88.25 109.27,97.45 108.56,98.15 108.56,104.67 109.31,105.41 v1(109.31,113.82)
  LY6 w0.121: v1(109.31,113.82) 91.92,113.82 87.98,117.76 26.96,117.76 25.06,119.67 25.06,126.28 v1(20.87,130.47)
UART1_RTS: length 156.7
  TOP w0.121: v1(20.87,131.74) U15.10 ; v2(104.33,72.13) U43.G15
  LY3 w0.102: v2(104.33,72.13) 104.33,71.68 104.73,71.29 104.73,71.12 105.36,70.48 107.86,70.48
  LY3 w0.121: 107.86,70.48 110.34,70.48 112.04,72.18 112.04,77.37 112.69,78.02 112.69,78.65 112.18,79.16 112.18,81.95 111.42,82.71 111.42,83.22 110.81,83.83 110.81,104.08 v1(111.67,104.94)
  LY6 w0.121: v1(111.67,104.94) 110.02,104.94 109.77,105.19 100.37,105.19 99.35,106.21 85.48,106.21 85.17,105.9 83.16,105.9 82.39,105.13 73.38,105.13 72.68,105.83 68.74,105.83 65.7,108.88 52.74,108.88 51.09,110.53 29.5,110.53 19.98,120.05 19.98,130.85 v1(20.87,131.74)
UART1_RXD: length 156.5
  TOP w0.121: v2(105.34,72.13) U43.G16 ; v1(20.87,134.28) U15.12
  LY3 w0.102: v2(105.34,72.13) 105.73,71.73 107.5,71.73 107.75,71.98 107.86,71.98
  LY3 w0.121: 107.86,71.98 110.08,71.98 v1(110.27,71.79) ; v1(109.38,104.6) 109.82,104.16 109.82,83.99 109.58,83.75 109.58,82.76 109.82,82.52 109.82,79.53 v1(109.38,79.09)
  LY6 w0.121: v1(109.38,104.6) 100.35,104.6 99.06,105.89 86.46,105.89 85.51,104.94 83.96,104.94 83.65,104.62 81.84,104.62 81.67,104.79 73.19,104.79 72.45,105.53 70.73,105.53 70.52,105.32 60.42,105.32 58.08,107.67 27.42,107.67 19.09,116 19.09,132.5 v1(20.87,134.28)
  BOTTOM w0.121: v1(110.27,71.79) 110.27,76.87 109.38,77.76 v1(109.38,79.09)
UART1_TXD: length 140.8
  TOP w0.121: v2(103.33,72.13) U43.G14 ; v1(20.87,133.01) U15.11
  LY3 w0.121: v1(67.73,106.08) 67.35,105.7 67.35,83.54 67.79,83.1 67.79,74.13 v1(67.35,73.7)
  LY6 w0.102: v2(103.33,72.13) 102.94,72.52 102.13,72.52 101.93,72.32 101.93,71.78 101.68,71.53 91.03,71.53 90.83,71.73 88.87,71.73 88.81,71.79
  LY6 w0.121: v1(20.87,133.01) 20.87,132.88 19.6,131.61 19.6,119.8 29.25,110.15 50.84,110.15 52.36,108.62 65.19,108.62 v1(67.73,106.08) ; 88.81,71.79 87.54,73.06 83.35,73.06 83.16,73.26 78.14,73.26 77.33,74.06 67.72,74.06 v1(67.35,73.7)
UART2_CTS: length 80.1
  TOP w0.121: v1(155.74,46.9) U19.9 ; v2(104.33,71.13) U43.H15
  LY3 w0.121: v1(154.4,72.74) 154.4,48.24 v1(155.74,46.9)
  LY6 w0.102: v2(104.33,71.13) 104.75,71.13 105.15,70.73 106.53,70.73 106.73,70.93 106.73,71.12 107.13,71.52 107.86,71.52
  LY6 w0.121: v1(154.4,72.74) 117.82,72.74 116.94,71.86 112.63,71.86 112.26,72.23 108.68,72.23 107.97,71.52 107.86,71.52
UART2_RTS: length 75.6
  TOP w0.121: v1(155.74,48.17) U19.10 ; v2(102.33,71.13) U43.H13
  LY6 w0.102: v1(105.26,70.08) 105.71,70.53 107.35,70.53 107.63,70.81 107.86,70.81
  LY6 w0.121: 107.86,70.81 146.82,70.81 157.08,60.55 157.08,49.51 v1(155.74,48.17)
  BOTTOM w0.102: v2(102.33,71.13) 102.78,71.13 103.17,71.52 104.55,71.52 104.74,71.32 104.74,70.59 v1(105.26,70.08)
UART2_RXD: length 69
  TOP w0.121: v1(155.61,50.71) U19.12 ; v2(103.33,71.13) U43.H14
  LY6 w0.102: 107.86,70.32 106.39,70.32 105.74,69.67 105.06,69.67 104.74,69.99 104.74,70.26 104.55,70.45 104.01,70.45 v2(103.33,71.13)
  LY6 w0.121: 107.86,70.32 108.79,70.32 109.02,70.56 144.27,70.56 155.61,59.22 v1(155.61,50.71)
UART2_TXD: length 64.4
  TOP w0.102: 107.86,71.74 107.74,71.63 U43.G18
  TOP w0.121: v1(155.74,49.44) U19.11 ; 107.86,71.74 108.62,72.5 109.76,72.5 110.39,73.14 110.39,73.3 111.09,74 v1(120.93,74)
  BOTTOM w0.121: v1(155.74,49.44) 136.44,68.74 121.57,68.74 120.93,69.38 v1(120.93,74)
UART3_CTS: length 59.2
  TOP w0.121: v2(103.33,70.13) U43.J14 ; v1(155.74,78.02) U22.9
  LY6 w0.102: v2(103.33,70.13) 103.33,70.57 102.94,70.96 102.94,71.29 103.17,71.52 105.33,71.52 105.73,71.92 105.73,72.12 106.13,72.52 107.26,72.52 107.47,72.72 107.86,72.72
  LY6 w0.121: v1(155.74,78.02) 154.14,76.41 116.3,76.41 112.61,72.72 107.86,72.72
UART3_RTS: length 58
  TOP w0.121: v1(155.74,79.29) U22.10 ; v2(106.34,71.13) U43.H17
  LY3 w0.121: v1(155.74,79.29) 155.13,78.68 v1(155.13,73.55)
  LY6 w0.102: 107.86,72.05 107.53,71.72 106.93,71.72 v2(106.34,71.13)
  LY6 w0.121: v1(155.13,73.55) 115.02,73.55 113.94,72.47 108.28,72.47 107.86,72.05
UART3_RXD: length 60.3
  TOP w0.121: v1(155.74,81.83) U22.12 ; v2(107.34,71.13) U43.H18
  LY6 w0.102: 107.86,71.13 v2(107.34,71.13)
  LY6 w0.121: v1(155.74,81.83) 156.18,81.38 156.18,73.89 153.39,71.1 108.44,71.1 108.41,71.13 107.86,71.13
UART3_TXD: length 60.2
  TOP w0.121: v2(105.34,71.13) U43.H16 ; v1(155.74,80.56) U22.11
  LY3 w0.102: 107.86,70.73 106.17,70.73 105.78,71.13 v2(105.34,71.13)
  LY3 w0.121: 107.86,70.73 110.22,70.73 111.75,72.26 111.75,77.94 v1(112.19,78.38)
  LY6 w0.121: v1(112.19,78.38) 113.67,79.86 155.05,79.86 v1(155.74,80.56)
VCAN0: length 25.9
  TOP w0.508: U16.8 157.14,144.06 157.64,144.56 157.64,145.71 ; 162.6,147.48 161.84,148.24 161.84,152.31 161.2,152.95 v1(161.07,152.95) U14.7 ; 162.6,147.48 161.29,146.17 v1(160.86,146.17) C54.1 159.89,146.21 158.15,146.21 157.64,145.71 ; 162.6,147.48 v1(165.54,147.48) J11.9 ; 157.64,145.71 156.76,146.6 v1(154.85,146.6) C52.1
VCPLD_INT: length 17.3
  TOP w0.508: v2(96.34,66.13) U43.M8 ; U43.K8 v2(96.34,68.13) ; U43.J9 v2(97.34,70.13) ; C145.1 v1(108.62,69.25) ; U43.J11 v2(100.34,70.13) ; U43.G11 v2(100.34,72.13) ; R160.1 v1(111.41,68.99) ; U43.K10 v2(99.34,68.13) ; U43.H12 v2(101.34,71.13) ; U43.L7 v2(95.34,67.13) ; C142.1 v1(111.31,73.55) ; C143.1 v1(108.62,73.44)
  BOTTOM w0.508: C140.1 97.19,68.98 v2(96.34,68.13) ; v2(97.34,70.13) 97.73,70.52 C138.1 ; C146.1 108.62,72.24 v1(108.62,71.54) ; C139.1 98.94,67.73 v2(99.34,68.13) 99.49,68.13 99.73,68.36 99.73,68.38 100.11,68.77 C141.1 100.34,69.35 v2(100.34,70.13) ; C145.1 v1(108.62,69.25)
VCPLD_VIO1: length 101.6
  TOP w0.508: U43.C1 v2(89.34,76.13) 89.32,76.11 85.76,76.11 84.49,74.84 68.11,74.84 66.84,76.11 65.44,76.11 64.43,77.13 57.64,77.13 55.66,75.14 C137.1 v1(54.39,74.21) J22.4 ; U43.K7 v2(95.34,68.13) ; U43.T1 v2(89.34,62.12) 86.69,62.12 86.04,62.78 C157.1 86,64.58 R162.1 R161.1 ; v1(40.55,71.67) 40.55,67.73 R153.2 ; v1(40.55,71.67) 40.55,73.44 R154.2 ; v1(40.55,71.67) R155.2 ; U43.J7 v2(95.34,70.13)
  LY6 w0.508: v1(40.55,71.67) 51.85,71.67 v1(54.39,74.21)
  BOTTOM w0.508: 88.68,75.48 88.68,69.13 C159.1 ; 88.68,75.48 C158.1 ; 88.68,75.48 v2(89.34,76.13) ; 95.29,69.13 95.34,69.17 v2(95.34,70.13) ; 95.29,69.13 C159.1 ; 95.29,69.13 95.34,69.08 v2(95.34,68.13) ; C159.1 88.68,68.36 88.05,67.73 C161.1 89.32,62.14 v2(89.34,62.12)
VCPLD_VIO2: length 41.8
  TOP w0.121: U43.G9 v2(97.34,72.13) ; U43.A3 v2(91.33,78.13) ; v2(99.34,72.13) U43.G10
  TOP w0.508: U43.A16 v2(105.34,78.13) 105.32,78.14 C151.1 105.42,81.56 R164.1 R163.1
  BOTTOM w0.508: C148.1 C150.1 105.96,78.75 v2(105.34,78.13) 104.56,78.9 98.59,78.9 98.34,78.65 ; 98.34,72.43 97.64,72.43 v2(97.34,72.13) ; 98.34,72.43 99.03,72.43 v2(99.34,72.13) ; 98.34,72.43 98.34,78.65 ; 91.99,79.67 93.33,79.67 93.64,79.97 97.01,79.97 98.34,78.65 ; 91.99,79.67 91.35,79.03 91.35,78.14 v2(91.33,78.13) ; 91.99,79.67 C149.1 C147.1
VCPLD_VIO3: length 36.2
  TOP w0.508: v2(107.34,62.12) U43.T18 ; U43.J12 v2(101.34,70.13) ; U43.K12 v2(101.34,68.13) ; R166.1 R165.1 111.31,77.28 C156.1 108.88,75.48 108.23,76.13 v2(107.34,76.13) U43.C18
  BOTTOM w0.508: 107.86,69.63 107.92,69.57 107.92,68.38 107.93,68.37 107.93,68.19 108.62,67.5 C153.1 107.97,62.12 v2(107.34,62.12) ; 107.86,69.63 C154.1 107.99,71.03 107.99,75.48 ; 107.86,69.63 106.84,69.63 106.34,69.13 C155.1 ; 107.99,75.48 v2(107.34,76.13) ; 107.99,75.48 C152.1 ; C155.1 102.02,69.44 v2(101.34,70.13) ; C155.1 102.02,68.81 v2(101.34,68.13)
VCPLD_VIO4: length 41.2
  TOP w0.305: U43.M10 v2(99.34,66.13) ; U43.M9 v2(97.34,66.13)
  TOP w0.508: R167.1 R168.1 106.49,56.16 C166.1 104.69,57.82 v1(105.32,58.46) 105.34,58.47 v2(105.34,60.13) U43.V16 ; U43.V3 v2(91.33,60.13)
  BOTTOM w0.508: v2(97.34,66.13) 97.83,65.63 98.21,65.63 ; 91.35,59.35 91.35,60.11 v2(91.33,60.13) ; 91.35,59.35 C165.1 C164.1 ; 91.35,59.35 98.21,59.35 ; v2(99.34,66.13) 98.84,65.63 98.21,65.63 ; 98.21,65.63 98.21,59.35 ; 98.21,59.35 99.1,58.46 v1(105.32,58.46) C162.1 C163.1
VEXPD: length 557.6
  TOP w0.381: C11.1 v1(40.04,88.05)
  TOP w0.635: v1(74.97,38.52) 74.21,38.52 C134.1 ; v1(105.32,153.96) C230.1 ; J4.19 105.45,125.51 C6.1 ; C227.1 v1(123.1,154.09)
  TOP w0.762: R131.2 v1(24.04,106.59) R135.2 ; R130.2 v1(24.04,111.67) R134.2 ; R136.2 v1(24.04,101.51) R132.2 ; R129.2 v1(24.04,116.75) R133.2
  TOP w1.016: v1(24.04,119.59) 27.13,119.59 27.85,120.31 R120.2 ; R125.2 v1(159.3,15.15) ; v1(123.1,154.09) U52.2 ; v1(105.32,153.96) U53.2
  BOTTOM w0.635: 4.48,20.23 R111.2 ; 31.79,20.23 R105.2 ; 9.56,20.23 R110.2 ; R104.2 36.23,20.23 ; 27.34,20.23 R106.2 ; 22.9,20.23 R107.2 ; 18.45,20.23 R108.2 ; 14.01,20.23 R109.2
  BOTTOM w1.016: 39.53,20.23 40.89,21.58 40.89,45.5 ; 39.53,20.23 39.53,9.94 41.44,8.04 41.44,5.63 45,2.07 149.52,2.07 159.3,11.85 v1(159.3,15.15) ; 39.53,20.23 4.48,20.23 ; 105.32,154.72 106.21,155.61 121.58,155.61 v1(123.1,154.09) 123.1,153.2 124.5,151.8 124.5,150.79 123.23,149.52 123.23,136.05 122.34,135.17 119.67,135.17 117.26,132.75 117.26,125.13 116.24,124.12 106.84,124.12 J4.19 ; 105.32,154.72 v1(105.32,153.96) ; 105.32,154.72 102.65,157.39 76.24,157.39 74.84,155.99 74.84,143.93 72.17,141.26 53.5,141.26 49.69,137.45 32.8,137.45 31.15,135.8 31.15,131.99 30.01,130.85 25.23,130.85 23.72,129.34 23.72,127.15 24.04,126.83 v1(24.04,119.59) v1(24.04,116.75) v1(24.04,111.67) v1(24.04,106.59) v1(24.04,101.51) 24.04,100.11 24.8,99.35 25.56,99.35 27.47,97.45 30.14,97.45 31.28,96.3 31.28,94.14 32.49,92.94 32.49,90.84 33.37,89.95 39.03,89.95 40.04,88.94 v1(40.04,88.05) 40.04,86.52 ; 40.04,86.52 41.44,86.52 43.09,84.87 43.09,84.37 43.85,83.6 51.22,83.6 51.35,83.48 51.35,54.14 50.2,53 43.85,53 40.89,50.03 40.89,45.5 ; 40.04,86.52 J6.1 ; 40.89,45.5 47.15,45.5 51.6,41.06 59.35,41.06 61.89,38.52 v1(74.97,38.52) J20.1
VGP_1_8D: length 7.6
  TOP w0.635: R241.2 106.65,150.21 107.35,150.21 107.8,149.77 C229.1 107.99,149.91 C228.1 R243.2 107.86,153.07 U53.4
VGP_1_8DEN: length 2.7
  TOP w0.121: U53.1 R242.1
VGP_1_8DFB: length 5.4
  TOP w0.121: R244.2 R243.1 ; R243.1 C228.2 ; R243.1 109.13,153.07 U53.5
VGP_3_3D: length 7.6
  TOP w0.635: R237.2 124.43,150.21 125.13,150.21 125.58,149.77 C226.1 125.77,149.91 125.77,152.95 125.64,153.07 U52.4
VGP_3_3DEN: length 2.7
  TOP w0.121: U52.1 R238.1
VGP_3_3DFB: length 5.4
  TOP w0.121: 128.31,151.68 C225.2 R239.1 126.91,153.07 U52.5
VSDMMC1: length 52.2
  TOP w0.381: v1(88.43,154.85) U26.10 ; v1(92.87,154.85) U25.10
  TOP w0.508: v1(90.08,161.84) 90.08,162.6 ; R51.2 R52.2 81.44,149.26 81.83,149.64 81.83,149.88 82.23,150.28 R50.2 R49.2 85,150.28 85.64,149.64 87.52,149.64 88.05,150.17 C78.1 88.05,150.82 v1(88.61,151.37) ; v1(89.46,151.41) 89.57,151.29 89.57,150.7 C79.1 ; R47.1 99.34,149.76 98.84,149.26 R48.2 v1(96.05,149.26) ; 91.35,162.6 v1(91.35,161.84) ; v1(88.81,161.84) 88.81,162.6 ; 87.54,162.6 v1(87.54,161.84) 87.54,158.41 88.43,157.52 v1(88.43,154.85)
  BOTTOM w0.508: v1(87.54,161.84) v1(88.81,161.84) v1(90.08,161.84) v1(91.35,161.84) ; v1(89.46,151.41) 89.42,151.37 v1(88.61,151.37) J15.19 ; v1(89.46,151.41) J15.4 ; v1(89.46,151.41) 90.35,152.31 92.62,152.31 ; 92.62,152.31 92.62,153.2 92.87,153.45 v1(92.87,154.85) 92.24,155.49 91.22,155.49 90.59,154.85 v1(88.43,154.85) ; 92.62,152.31 93.13,151.8 95.54,151.8 96.05,151.29 v1(96.05,149.26)
WAKEUP_SW: length 39
  TOP w0.121: R127.1 C130.1 39.28,6.77 39.71,7.2 v1(40.23,7.2) SW7.1 ; U42.1 60.5,25.33 v1(60.49,25.31) ; SW7.2 v1(41.09,14.68)
  LY3 w0.121: v1(41.09,14.68) 40.23,13.82 v1(40.23,7.2)
  LY6 w0.121: v1(60.49,25.31) 51.02,15.84 42.25,15.84 v1(41.09,14.68)
N16791163: length 4.6
  TOP w0.121: C53.1 16.17,138.47 15.79,138.09 U15.2
N16791168: length 2.1
  TOP w0.121: C56.1 12.61,133.01 U15.6
N16791228: length 2.1
  TOP w0.121: C55.2 12.61,134.28 U15.5
N16791231: length 2.1
  TOP w0.121: U15.4 12.61,135.55 C55.1
N16791234: length 2.4
  TOP w0.121: U15.3 13.25,136.82 C50.2
N16791237: length 2.4
  TOP w0.121: U15.1 13.25,139.36 C50.1
N16791926: length 4.7
  TOP w0.121: U19.2 153.83,54.52 154.09,54.77 C63.1
N16791930: length 2.7
  TOP w0.121: U19.6 149.9,49.44 C68.1
N16791942: length 2.7
  TOP w0.121: C64.2 149.9,50.71 U19.5
N16791944: length 2.7
  TOP w0.121: U19.4 149.9,51.98 C64.1
N16791946: length 3
  TOP w0.121: C62.2 150.53,53.25 U19.3
N16791948: length 3
  TOP w0.121: U19.1 150.53,55.79 C62.1
N16792432: length 4.7
  TOP w0.121: C74.1 154.09,85.89 153.83,85.64 152.45,85.64
N16792436: length 2.7
  TOP w0.121: U22.6 149.9,80.56 C76.1
N16792448: length 2.7
  TOP w0.121: U22.5 149.9,81.83 C75.2
N16792450: length 2.7
  TOP w0.121: C75.1 149.9,83.1 152.45,83.1
N16792452: length 3
  TOP w0.121: U22.3 150.53,84.37 C73.2
N16792454: length 3
  TOP w0.121: C73.1 150.53,86.91 U22.1
N16816822: length 4.3
  TOP w0.121: v2(105.15,99.97) U3.B4
  BOTTOM w0.102: R16.1 R17.2 105.51,99.61 v2(105.15,99.97)
N16828302: length 2.8
  TOP w0.121: U39.2 v1(54.17,39.54)
  BOTTOM w0.121: v1(54.17,39.54) 54.17,39.53 54.77,39.53 55.03,39.28 R103.2
N16828557: length 2.1
  TOP w0.121: U40.2 v1(54.17,29.38)
  BOTTOM w0.121: v1(54.17,29.38) 54.39,29.15 R102.1
N16829115: length 2.3
  TOP w0.121: v1(63.66,90.97) 63.41,91.22 U9.7
  BOTTOM w0.121: v1(63.66,90.97) 63.66,91.6 63.28,91.99
N16829117: length 2.6
  TOP w0.121: v1(64.68,90.59) 63.91,91.36 U9.8
  BOTTOM w0.121: v1(64.68,90.59) R25.1
N16843552: length 2.6
  TOP w0.121: R33.2 63.74,105.14 U13.6
N16843557: length 2.6
  TOP w0.121: U13.7 63.09,105.14 R32.2
N16875858: length 4.5
  TOP w0.102: J6.12 37.88,79.54 39.36,79.54
  TOP w0.121: 39.36,79.54 39.92,79.54 40.3,79.92 R12.1
N16973002: length 9
  TOP w0.121: J20.12 82.84,36.23 83.1,35.98 R145.1
N16980972: length 3.2
  TOP w0.121: Q11.D 29,115.63 D9.1
N16980976: length 4.1
  TOP w0.121: R129.1 24.93,115.86 24.93,117.64 25.16,117.87 D9.2
N16981022: length 3.2
  TOP w0.121: D10.1 26.07,110.67 Q12.D
N16981031: length 4.2
  TOP w0.121: D10.2 25.04,112.79 24.8,112.56 24.8,110.65 R130.1
N16981067: length 4.2
  TOP w0.121: R131.1 24.8,105.57 24.8,107.48 25.04,107.71 D11.2
N16981069: length 3.2
  TOP w0.121: D11.1 29,105.47 Q13.D
N16981098: length 3.2
  TOP w0.121: D12.1 26.07,100.51 Q14.D
N16981109: length 4.2
  TOP w0.121: R132.1 24.8,100.49 24.8,102.4 25.04,102.63 D12.2
N16982295: length 4.5
  TOP w0.121: D13.1 17.81,115.63 Q15.D
N16982308: length 2.2
  TOP w0.121: D13.2 22.79,118.53 R133.1
N16982335: length 4.5
  TOP w0.121: D14.1 22.01,110.67 20.45,110.67 20.44,110.66 20.02,110.66 20.01,110.67 Q16.D
N16982342: length 2.2
  TOP w0.121: D14.2 22.79,113.45 R134.1
N16982376: length 4.5
  TOP w0.121: D15.1 17.81,105.47 Q17.D
N16982380: length 2.2
  TOP w0.121: D15.2 22.79,108.37 R135.1
N16982414: length 4.5
  TOP w0.121: D16.1 17.81,100.39 Q18.D
N16982428: length 2.2
  TOP w0.121: D16.2 22.79,103.29 R136.1
N17077837: length 5.1
  TOP w0.121: U51.3 68.08,148.02 69.51,146.6 69.51,145.96 70.14,145.33 C209.1
N17077840: length 41.7
  TOP w0.121: C209.2 v1(72.3,145.33) ; J27.2 v1(43.84,153.98)
  BOTTOM w0.121: v1(43.84,153.98) 49.96,153.98 53.38,157.39 65.95,157.39 70.4,152.95 70.4,146.09 71.16,145.33 v1(72.3,145.33)
N17077863: length 4.4
  TOP w0.121: C210.1 70.01,146.6 68.09,148.52 U51.4
N17077921: length 4.1
  TOP w0.121: C211.1 69.76,147.87 68.61,149.02 U51.5
N17077923: length 35.4
  TOP w0.121: C211.2 72.3,147.87 73.57,149.14 73.57,156.88 67.03,163.42 J27.3
N17077933: length 3.8
  TOP w0.121: U51.6 68.87,149.52 69.25,149.14 C212.1
N17102954: length 3.4
  TOP w0.121: v1(58.15,149.77) 58.76,149.77 59.01,150.02 U51.30
  BOTTOM w0.121: v1(58.15,149.77) 57.57,149.77 C199.1
N17102959: length 3.5
  TOP w0.121: v1(58.71,150.41) 58.83,150.52 U51.29
  BOTTOM w0.121: v1(58.71,150.41) 58.2,150.91 57.44,150.91 C200.1
N17102964: length 4
  TOP w0.121: U51.32 59.36,149.02 59.11,148.77 58.21,148.77 v1(58,148.98)
  BOTTOM w0.121: v1(58,148.98) 58.86,148.12 59.47,148.12
N17102969: length 2.2
  TOP w0.121: U51.31 58.99,149.52 v1(58.69,149.21)
  BOTTOM w0.121: v1(58.69,149.21) 58.74,149.26 59.47,149.26
N17102974: length 5.3
  TOP w0.121: U51.10 67.95,151.52 69.25,152.82 69.25,153.83 69.63,154.22 C221.1
N17103265: length 4.4
  TOP w0.121: U51.9 68.09,151.02 70.01,152.95 C222.1
N17103270: length 3.3
  TOP w0.121: U51.28 58.22,151.02 v1(57.61,150.41) C223.1
N17103275: length 3.1
  TOP w0.121: C224.1 v1(57.61,151.68) 57.76,151.52 U51.27
N17104420: length 4.3
  TOP w0.121: U51.14 65.66,153.8 67.22,155.36 C207.1
N17104425: length 6
  TOP w0.121: C206.1 69.63,155.49 69,154.85 69,153.2 67.82,152.02 U51.11
N17104572: length 3.8
  TOP w0.121: U51.7 68.87,150.02 69.25,150.41 C205.1
N17104759: length 4.1
  TOP w0.121: U51.8 68.48,150.52 69.63,151.68 C208.1
N17104819: length 2.2
  TOP w0.121: Y5.1 69.75,76.23 R229.2
N17104913: length 3.7
  TOP w0.121: R230.2 R231.2 74.83,77.25 Y5.3
N17284396: length 3.2
  TOP w0.121: D1.1 35.74,21.38 Q1.D
N17284409: length 2.8
  TOP w0.121: v1(37.86,22.75) D1.2
  BOTTOM w0.121: R104.1 37.86,22.12 v1(37.86,22.75)
N17284436: length 3.2
  TOP w0.121: D2.1 31.29,21.38 Q2.D
N17284443: length 2.5
  TOP w0.121: v1(33.42,22.62) D2.2
  BOTTOM w0.121: v1(33.42,22.62) 33.42,22.12 R105.1
N17284477: length 3.2
  TOP w0.121: D3.1 26.85,21.38 Q3.D
N17284481: length 2.8
  TOP w0.121: v1(28.97,22.75) D3.2
  BOTTOM w0.121: v1(28.97,22.75) 28.97,22.12 R106.1
N17284515: length 3.2
  TOP w0.121: Q4.D 22.4,21.38 D4.1
N17284529: length 2.5
  TOP w0.121: v1(24.53,22.62) D4.2
  BOTTOM w0.121: 23.91,21.5 24.53,22.12 v1(24.53,22.62)
N17284999: length 3.2
  TOP w0.121: Q5.D 17.96,21.38 D5.1
N17285012: length 2.5
  TOP w0.121: v1(20.08,22.62) D5.2
  BOTTOM w0.121: v1(20.08,22.62) 20.08,22.12 R108.1
N17285039: length 3.2
  TOP w0.121: D6.1 13.51,21.38 Q6.D
N17285046: length 2.5
  TOP w0.121: v1(15.64,22.62) D6.2
  BOTTOM w0.121: R109.1 15.64,22.12 v1(15.64,22.62)
N17285080: length 3.2
  TOP w0.121: Q7.D 9.07,21.38 D7.1
N17285084: length 2.5
  TOP w0.121: v1(11.19,22.62) D7.2
  BOTTOM w0.121: v1(11.19,22.62) 11.19,22.12 R110.1
N17285118: length 3.2
  TOP w0.121: Q8.D 3.99,21.38 D8.1
N17285132: length 2.5
  TOP w0.121: v1(6.11,22.62) D8.2
  BOTTOM w0.121: R111.1 6.11,22.12 v1(6.11,22.62)
N17523832: length 1.7
  TOP w0.121: v2(95.34,77.13) U43.B7
  BOTTOM w0.102: TP80.1 95.29,77.17 v2(95.34,77.13)
N17523835: length 3
  TOP w0.121: v2(96.34,77.13) U43.B8
  BOTTOM w0.102: 96.68,78.65 96.81,78.52 96.81,77.63 96.34,77.16 v2(96.34,77.13)
  BOTTOM w0.121: TP81.1 96.68,78.65
N17543166: length 3
  TOP w0.121: R157.2 73.74,66.59 Y2.3
N17543396: length 1.9
  TOP w0.121: R152.2 71.03,62.9 Y2.1
N17609291: length 14.4
  TOP w0.102: 99.7,78.65 99.84,78.52 U43.A11
  TOP w0.121: 99.7,78.65 97.62,80.73 97.62,84.67 96.99,85.3 94.72,85.3 94.46,85.56 94.46,87.48 TP15.1
N17609340: length 4.4
  TOP w0.102: 100.84,78.65 U43.A12
  TOP w0.121: 100.84,78.65 100.84,80.47 100.24,81.06 TP20.1
N17609367: length 6.8
  TOP w0.102: 101.84,78.65 U43.A13
  TOP w0.121: 101.84,78.65 101.84,80.26 101.13,80.96 101.13,82.71 TP22.1
N17609868: length 14.7
  TOP w0.121: v1(105.03,85.23) 103.26,83.46 103.26,83.25 102.92,82.9 102.92,82.6 TP16.1 ; v2(104.33,76.13) U43.C15
  LY3 w0.102: 104.83,78.65 104.83,76.98 104.33,76.48 v2(104.33,76.13)
  LY3 w0.121: 104.83,78.65 104.83,85.03 v1(105.03,85.23)
